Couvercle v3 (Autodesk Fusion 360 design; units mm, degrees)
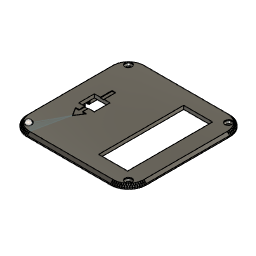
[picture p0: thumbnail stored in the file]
base_feature "Fonction de base" bodies "Corps de maillage1"
scale "Echelle" ScaleFactor 0.1
align "Aligner1"
align "Aligner2"
align "Aligner3"
move "Déplacer"
sketch "Esquisse1" plane through (0, 0, 0) normal (0, 0, 1) x axis (-1, 0, 0)
  line L1 (41.134, 41.5) -> (28.65, 18.35)
  line L2 (35, 48) -> (41.134, 41.5)
  line L3 (28.65, 18.35) -> (35, 48)
  circle C1 centre (41.9941, 42.0034) radius 0.9966
  point P3 (41.134, 41.5)
  coincident P3 C1
work_axis "Axe de construction"
work_plane "Plan de construction"
sketch "Esquisse2" plane through (0, 0, 0) normal (0.7072, -0.707, 0) x axis (0.707, 0.7072, 0)
  line L1 (-59.3952, 3.3136) -> (-59.3952, 0)
  line L2 (-61.1452, -5) -> (-59.3952, -5)
  line L3 (-61.1452, -2) -> (-61.1452, -5)
  line L4 (-62.3702, -0.8) -> (-61.1452, -2)
  line L5 (-59.3952, -5) -> (-59.3952, 0)
  line L6 (-60.3918, 0) -> (-58.3986, 0)
  line L7 (-62.3702, 0) -> (-62.3702, -0.8)
  line L8 (-59.3952, 0) -> (-62.3702, 0)
  point P2 (-59.3952, 0)
  point P4 (-59.3952, 0)
  point P14 (-59.3952, 0)
  point P12 (-59.3952, 0)
  point P11 (-59.3952, 0)
  point P8 (-62.3702, -0.8)
  point P13 (-62.3702, 0)
  point P7 (-61.1452, -2)
  vertical L1
  coincident P2 P4
  horizontal L2
  perpendicular L2 L3
  coincident L1 P14
  vertical L5
  coincident L1 P14
  perpendicular L1 L8
  vertical L7
  coincident P12 P14
  dimension "d2" = 3.5
  dimension "d5" distance L2 P11 = 5
  dimension "d13" = 5.95
  dimension "d14" distance P8 P13 = 0.8
  dimension "d15" distance P7 L8 = 2
revolve "Révolution" sketch "Esquisse2" AlongAngle 360
circular_pattern "Réseau C" TotalAngle 360
sketch "Esquisse3" plane through (0, 0, -3) normal (0, 0, -1) x axis (1, 0, 0)
  line L1 (-20.1, -0.45) -> (-20.0659, -0.7088)
  line L2 (-20.1, 8.55) -> (-20.1, -0.45)
  line L3 (-37.2, 8.55) -> (-20.1, 8.55)
  line L4 (-37.2, -0.45) -> (-37.2, 8.55)
  line L5 (-37.2341, -0.7088) -> (-37.2, -0.45)
  line L6 (-37.334, -0.95) -> (-37.2341, -0.7088)
  line L7 (-37.4929, -1.1571) -> (-37.334, -0.95)
  line L8 (-37.7, -1.316) -> (-37.4929, -1.1571)
  line L9 (-37.9412, -1.4159) -> (-37.7, -1.316)
  line L10 (-38.2, -1.45) -> (-37.9412, -1.4159)
  line L11 (-46.8, -1.45) -> (-38.2, -1.45)
  line L12 (-47.0588, -1.4159) -> (-46.8, -1.45)
  line L13 (-47.3, -1.316) -> (-47.0588, -1.4159)
  line L14 (-47.5071, -1.1571) -> (-47.3, -1.316)
  line L15 (-47.666, -0.95) -> (-47.5071, -1.1571)
  line L16 (-47.7659, -0.7088) -> (-47.666, -0.95)
  line L17 (-47.8, -0.45) -> (-47.7659, -0.7088)
  line L18 (-47.8, 23.15) -> (-47.8, -0.45)
  line L19 (-47.7659, 23.4088) -> (-47.8, 23.15)
  line L20 (-47.666, 23.65) -> (-47.7659, 23.4088)
  line L21 (-47.5071, 23.8571) -> (-47.666, 23.65)
  line L22 (-47.3, 24.016) -> (-47.5071, 23.8571)
  line L23 (-47.0588, 24.1159) -> (-47.3, 24.016)
  line L24 (-46.8, 24.15) -> (-47.0588, 24.1159)
  line L25 (-11.5, 24.15) -> (-46.8, 24.15)
  line L26 (-11.2412, 24.1159) -> (-11.5, 24.15)
  line L27 (-11, 24.016) -> (-11.2412, 24.1159)
  line L28 (-10.7929, 23.8571) -> (-11, 24.016)
  line L29 (-10.634, 23.65) -> (-10.7929, 23.8571)
  line L30 (-10.5341, 23.4088) -> (-10.634, 23.65)
  line L31 (-10.5, 23.15) -> (-10.5341, 23.4088)
  line L32 (-10.5, -0.45) -> (-10.5, 23.15)
  line L33 (-10.5341, -0.7088) -> (-10.5, -0.45)
  line L34 (-10.634, -0.95) -> (-10.5341, -0.7088)
  line L35 (-10.7929, -1.1571) -> (-10.634, -0.95)
  line L36 (-11, -1.316) -> (-10.7929, -1.1571)
  line L37 (-11.2412, -1.4159) -> (-11, -1.316)
  line L38 (-11.5, -1.45) -> (-11.2412, -1.4159)
  line L39 (-19.1, -1.45) -> (-11.5, -1.45)
  line L40 (-19.3588, -1.4159) -> (-19.1, -1.45)
  line L41 (-19.6, -1.316) -> (-19.3588, -1.4159)
  line L42 (-19.8071, -1.1571) -> (-19.6, -1.316)
  line L43 (-19.966, -0.95) -> (-19.8071, -1.1571)
  line L44 (-20.0659, -0.7088) -> (-19.966, -0.95)
  line L45 (-45.037, -46.1472) -> (-46.1472, -45.037)
  line L46 (-43.8168, -47.1353) -> (-45.037, -46.1472)
  line L47 (-42.5, -47.9904) -> (-43.8168, -47.1353)
  line L48 (-41.101, -48.7032) -> (-42.5, -47.9904)
  line L49 (-39.6353, -49.2658) -> (-41.101, -48.7032)
  line L50 (-38.1187, -49.6722) -> (-39.6353, -49.2658)
  line L51 (-36.5679, -49.9178) -> (-38.1187, -49.6722)
  line L52 (-35, -50) -> (-36.5679, -49.9178)
  line L53 (35, -50) -> (-35, -50)
  line L54 (36.5679, -49.9178) -> (35, -50)
  line L55 (38.1187, -49.6722) -> (36.5679, -49.9178)
  line L56 (39.6353, -49.2658) -> (38.1187, -49.6722)
  line L57 (41.1011, -48.7032) -> (39.6353, -49.2658)
  line L58 (42.5, -47.9904) -> (41.1011, -48.7032)
  line L59 (43.8168, -47.1353) -> (42.5, -47.9904)
  line L60 (45.037, -46.1472) -> (43.8168, -47.1353)
  line L61 (46.1472, -45.037) -> (45.037, -46.1472)
  line L62 (47.1353, -43.8168) -> (46.1472, -45.037)
  line L63 (47.9904, -42.5) -> (47.1353, -43.8168)
  line L64 (48.7032, -41.1011) -> (47.9904, -42.5)
  line L65 (49.2658, -39.6353) -> (48.7032, -41.1011)
  line L66 (49.6722, -38.1187) -> (49.2658, -39.6353)
  line L67 (49.9178, -36.5679) -> (49.6722, -38.1187)
  line L68 (50, -35) -> (49.9178, -36.5679)
  line L69 (50, 35) -> (50, -35)
  line L70 (49.9178, 36.5679) -> (50, 35)
  line L71 (49.6722, 38.1187) -> (49.9178, 36.5679)
  line L72 (49.2658, 39.6353) -> (49.6722, 38.1187)
  line L73 (48.7032, 41.101) -> (49.2658, 39.6353)
  line L74 (47.9904, 42.5) -> (48.7032, 41.101)
  line L75 (47.1353, 43.8168) -> (47.9904, 42.5)
  line L76 (46.1472, 45.037) -> (47.1353, 43.8168)
  line L77 (45.037, 46.1472) -> (46.1472, 45.037)
  line L78 (43.8168, 47.1353) -> (45.037, 46.1472)
  line L79 (42.5, 47.9904) -> (43.8168, 47.1353)
  line L80 (41.1011, 48.7032) -> (42.5, 47.9904)
  line L81 (39.6353, 49.2658) -> (41.1011, 48.7032)
  line L82 (38.1187, 49.6722) -> (39.6353, 49.2658)
  line L83 (36.5679, 49.9178) -> (38.1187, 49.6722)
  line L84 (35, 50) -> (36.5679, 49.9178)
  line L85 (-35, 50) -> (35, 50)
  line L86 (-36.5679, 49.9178) -> (-35, 50)
  line L87 (-38.1187, 49.6722) -> (-36.5679, 49.9178)
  line L88 (-39.6353, 49.2658) -> (-38.1187, 49.6722)
  line L89 (-41.101, 48.7032) -> (-39.6353, 49.2658)
  line L90 (-42.5, 47.9904) -> (-41.101, 48.7032)
  line L91 (-43.8168, 47.1353) -> (-42.5, 47.9904)
  line L92 (-45.037, 46.1472) -> (-43.8168, 47.1353)
  line L93 (-46.1472, 45.037) -> (-45.037, 46.1472)
  line L94 (-47.1353, 43.8168) -> (-46.1472, 45.037)
  line L95 (-47.9904, 42.5) -> (-47.1353, 43.8168)
  line L96 (-48.7032, 41.101) -> (-47.9904, 42.5)
  line L97 (-49.2658, 39.6353) -> (-48.7032, 41.101)
  line L98 (-49.6722, 38.1187) -> (-49.2658, 39.6353)
  line L99 (-49.9178, 36.5679) -> (-49.6722, 38.1187)
  line L100 (-50, 35) -> (-49.9178, 36.5679)
  line L101 (-50, -35) -> (-50, 35)
  line L102 (-49.9178, -36.5679) -> (-50, -35)
  line L103 (-49.6722, -38.1187) -> (-49.9178, -36.5679)
  line L104 (-49.2658, -39.6353) -> (-49.6722, -38.1187)
  line L105 (-48.7032, -41.1011) -> (-49.2658, -39.6353)
  line L106 (-47.9904, -42.5) -> (-48.7032, -41.1011)
  line L107 (-47.1353, -43.8168) -> (-47.9904, -42.5)
  line L108 (-46.1472, -45.037) -> (-47.1353, -43.8168)
  line L109 (10.6815, 35.675) -> (10.6815, -35.675)
  line L110 (34.9315, 35.675) -> (10.6815, 35.675)
  line L111 (34.9315, -35.675) -> (34.9315, 35.675)
  line L112 (10.6815, -35.675) -> (34.9315, -35.675)
  line L113 (-19.8071, -4.1429) -> (-19.966, -4.35)
  line L114 (-19.6, -3.984) -> (-19.8071, -4.1429)
  line L115 (-19.3588, -3.8841) -> (-19.6, -3.984)
  line L116 (-19.1, -3.85) -> (-19.3588, -3.8841)
  line L117 (-8.1, -3.85) -> (-19.1, -3.85)
  line L118 (-8.1, 29.55) -> (-8.1, -3.85)
  line L119 (-46.8, 29.55) -> (-8.1, 29.55)
  line L120 (-47.0588, 29.5841) -> (-46.8, 29.55)
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  dimension "d16" = 0.2
extrude "Extrusion1" cut sketch "Esquisse3" no distance stored
sketch "Esquisse4" plane through (0, 0, -1) normal (0, 0, 1) x axis (-1, 0, 0)
  line L1 (30.15, 6.55) -> (27.15, 6.55)
  line L2 (30.15, 11.35) -> (30.15, 6.55)
  line L3 (33.15, 11.35) -> (30.15, 11.35)
  line L4 (28.65, 18.35) -> (33.15, 11.35)
  line L5 (24.15, 11.35) -> (28.65, 18.35)
  line L6 (27.15, 11.35) -> (24.15, 11.35)
  line L7 (27.15, 6.55) -> (27.15, 11.35)
  line L8 (27.15, -6.55) -> (30.15, -6.55)
  line L9 (27.15, -16.35) -> (27.15, -6.55)
  line L10 (30.15, -16.35) -> (27.15, -16.35)
  line L11 (30.15, -6.55) -> (30.15, -16.35)
extrude "Extrusion2" add sketch "Esquisse4" along normal blind 0.5
named bodies: "Corps de maillage1"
